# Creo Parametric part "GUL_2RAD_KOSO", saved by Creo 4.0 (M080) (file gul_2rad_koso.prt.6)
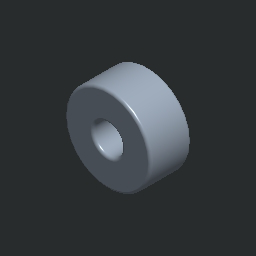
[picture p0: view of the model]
Units: millimeter Kilogram Sec (mmKs); MM, KILOGRAM, SECS
Materials in the file: OCEL_N

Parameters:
  MFG_WP_MATERIAL = "RO5_6"
  NAZOV = "GUL_2RAD_KOSO"
  PTC_MATERIAL_NAME = "OCEL_N"

Other parameters: HMOTNOST, HUSTOTA

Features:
  1. round

Named dimensions: velke_D

Layers: 1, 2, 3, 4, 5, 6, 7, 8, 9, 10, 11, 12, 13, 14, 15, 16, 17, 18, 19, 20, 21, 22, 23, 24, 25, 26, 27, 28, 29, 30, 31, 32

Family table entries: GENERIC, LOZISKO_3200, GUL_2RAD_KOSO, value(d_val), 2/>, value(i_val), LOZISKO_3201, GUL_2RAD_KOSO, !/(, 2/@, LOZISKO_3202, GUL_2RAD_KOSO, !/., LOZISKO_3302, GUL_2RAD_KOSO, !/., 2/E, 2/3, LOZISKO_3203, GUL_2RAD_KOSO, !/1, 2/D, LOZISKO_3303, GUL_2RAD_KOSO, !/1, LOZISKO_3204, GUL_2RAD_KOSO, !/4, LOZISKO_3304, GUL_2RAD_KOSO, !/4, 2/J, LOZISKO_3205, GUL_2RAD_KOSO, !/9, 2/J, LOZISKO_3305, GUL_2RAD_KOSO, !/9, 2/O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

Surfaces: 8 torus, 2 plane, 2 cylinder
